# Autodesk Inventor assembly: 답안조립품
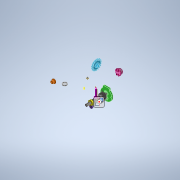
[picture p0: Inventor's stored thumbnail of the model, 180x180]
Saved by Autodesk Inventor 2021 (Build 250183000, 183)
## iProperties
Created: 2022-08
Part Number: 답안조립품
Document SubType Name: Assembly
Designer: Owner
Author: Owner
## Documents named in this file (16)
- C:\Users\Owner\Desktop\720810V1009\답안조립품.iam
- C:\Users\Owner\Desktop\720810V1009\본체.ipt
- C:\Users\Owner\Desktop\720810V1009\멈춤나사 M3.ipt
- C:\Users\Owner\Desktop\720810V1009\메인 축.ipt
- C:\Users\Owner\Desktop\720810V1009\베어링 608.ipt
- C:\Users\Owner\Desktop\720810V1009\베어링 6003.ipt
- C:\Users\Owner\Desktop\720810V1009\볼트 M4 x 10.ipt
- C:\Users\Owner\Desktop\720810V1009\부시.ipt
- C:\Users\Owner\Desktop\720810V1009\상부 캡.ipt
- C:\Users\Owner\Desktop\720810V1009\서브 축.ipt
- C:\Users\Owner\Desktop\720810V1009\스프로킷.ipt
- C:\Users\Owner\Desktop\720810V1009\슬라이더.ipt
- C:\Users\Owner\Desktop\720810V1009\오일 실 8 x 22 x 7.ipt
- C:\Users\Owner\Desktop\720810V1009\오일 실 17 x 32 x 8.ipt
- C:\Users\Owner\Desktop\720810V1009\커버.ipt
- C:\Users\Owner\Desktop\720810V1009\키 5 x 5.ipt
